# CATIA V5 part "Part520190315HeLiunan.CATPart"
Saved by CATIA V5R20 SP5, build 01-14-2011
Part number: 饮料瓶
Bounding box of the stored display mesh (mm): x -25 to 25, y -25 to 27, z 0 to 100
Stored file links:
  E:\180131213何浏楠\Part520190315HeLiunan.CATPart
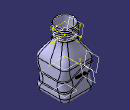
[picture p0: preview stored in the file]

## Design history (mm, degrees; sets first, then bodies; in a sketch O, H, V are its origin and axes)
Set1
  Sketch1 on xy-plane, origin (0, 0, 0), H (1, 0, 0), V (0, 1, 0)
    line L1 (25, 25) -> (25, -25)
    line L2 (25, -25) -> (-25, -25)
    line L3 (-25, -25) -> (-25, 25)
    line L4 (-25, 25) -> (25, 25)
    length L4 = 50
    length L1 = 50
    vertical: L1 V, L3 V
    horizontal: L2 H, L4 H
    equidistance: L1 L3 O, L2 L4 O
  Sketch2 on face of Pad1 from Sketch1.L2, origin (0, -25, 0), H (1, 0, 0), V (0, 0, 1)
    spline S1 through (-40, 20) (-11.6241, 30.786) (12.3742, 19.786) (40, 20)
  Extrude1: Element1 Sketch2, Lim1 69, Lim2 69
  MultiSel1: CommonCtxFeats ({extract ExtractElem face of Fillet1}; {extract ExtractElem face of Pad1 from Sketch1.L1}; {extract ExtractElem face of Pad1 from Sketch1.L2}; {extract ExtractElem face of Fillet1}; {extract ExtractElem face of Fillet1}; {extract ExtractElem face of Pad1 from Sketch1.L4}; {extract ExtractElem face of Fillet1}; {extract ExtractElem face of Pad1 from Sketch1.L3})
  Sketch3 on face of Pad1 from Sketch1.L2, origin (0, -25, 0), H (1, 0, 0), V (0, 0, 1)
    spline S1 through (-30.294, 40.4604) (-11.9151, 45.3274) (15.3659, 35.3071) (46.3801, 31.0127)
  Extrude2: Element1 Sketch3, Lim1 69, Lim2 69
  MultiSel2: CommonCtxFeats ({extract ExtractElem face of Fillet1}; {extract ExtractElem edge [face of Pad1 from Sketch1.L1 | face of Fillet1]}; {extract ExtractElem face of Pad1 from Sketch1.L1}; {extract ExtractElem face of Pad1 from Sketch1.L2}; {extract ExtractElem face of Fillet1}; {extract ExtractElem face of Fillet1}; {extract ExtractElem face of Pad1 from Sketch1.L4}; {extract ExtractElem face of Fillet1}; {extract ExtractElem face of Pad1 from Sketch1.L3})
  Join1: Elements ({intersect ToIntersect1 {extract ExtractElem face of Pad1 from Sketch1.L2}, ToIntersect2 Extrude1}; {intersect ToIntersect1 {extract ExtractElem face of Fillet1}, ToIntersect2 Extrude1}; {intersect ToIntersect1 {extract ExtractElem face of Fillet1}, ToIntersect2 Extrude1}; {intersect ToIntersect1 {extract ExtractElem face of Pad1 from Sketch1.L1}, ToIntersect2 Extrude1}; {intersect ToIntersect1 {extract ExtractElem face of Fillet1}, ToIntersect2 Extrude1}; {intersect ToIntersect1 {extract ExtractElem face of Pad1 from Sketch1.L4}, ToIntersect2 Extrude1}; {intersect ToIntersect1 {extract ExtractElem face of Fillet1}, ToIntersect2 Extrude1}; {intersect ToIntersect1 {extract ExtractElem face of Pad1 from Sketch1.L3}, ToIntersect2 Extrude1})
  Join2: Elements ({intersect ToIntersect1 {extract ExtractElem face of Pad1 from Sketch1.L2}, ToIntersect2 Extrude2}; {intersect ToIntersect1 {extract ExtractElem face of Fillet1}, ToIntersect2 Extrude2}; {intersect ToIntersect1 {extract ExtractElem face of Pad1 from Sketch1.L1}, ToIntersect2 Extrude2}; {intersect ToIntersect1 {extract ExtractElem face of Fillet1}, ToIntersect2 Extrude2}; {intersect ToIntersect1 {extract ExtractElem face of Pad1 from Sketch1.L4}, ToIntersect2 Extrude2}; {intersect ToIntersect1 {extract ExtractElem face of Fillet1}, ToIntersect2 Extrude2}; {intersect ToIntersect1 {extract ExtractElem face of Pad1 from Sketch1.L3}, ToIntersect2 Extrude2}; {intersect ToIntersect1 {extract ExtractElem face of Fillet1}, ToIntersect2 Extrude2})
  Plane1: type Normal, Curve Join2, RefPoint vertex [face of MultiSel2 | face of MultiSel2]
  Circle1: type CtrRad, Start 0, End 180, Center vertex [face of MultiSel2 | face of MultiSel2], Support Plane1, Radius 1, FirstDirection (0, 1, 0)
Body1 (main body)
  Pad1: profile Sketch1, direction (0, 0, 1), length 50
  Fillet1: on edge [face of Pad1 from Sketch1.L3 | face of Pad1 from Sketch1.L4]; edge [face of Pad1 from Sketch1.L1 | face of Pad1 from Sketch1.L2]; edge [face of Pad1 from Sketch1.L4 | face of Pad1 from Sketch1.L1]; edge [face of Pad1 from Sketch1.L2 | face of Pad1 from Sketch1.L3]
  Fillet2: on edge [start face of Pad1 | face of Fillet1]
  Plane2: type Offset, RefPlane xy-plane, Offset 40
  Plane3: type Offset, RefPlane Plane2, Offset 40
  Sketch4 on Plane3, origin (0, 0, 80), H (1, 0, 0), V (0, 1, 0)
    circle A1 centre (0, 0) radius 15
    radius A1 = 15
  Pad2: profile Sketch4, direction (0, 0, 1), length 20
  Sketch5 on end face of Pad1, origin (0, 0, 50), H (1, 0, 0), V (0, 1, 0)
    point P1 (25, 0)
    distance V P1 = 25
    coincidence: P1 H
  Sketch6 on start face of Pad2, origin (0, 0, 80), H (1, 0, 0), V (0, -1, 0)
    point P1 (15, 0)
    distance V P1 = 15
    coincidence: P1 H
  Loft1: solid, Sections ({boundary Boundary {extract ExtractElem end face of Pad1}}; {boundary Boundary {extract ExtractElem start face of Pad2}}), StartFace end face of Pad1, EndFace start face of Pad2
  Slot1: profile Circle1, centre curve Join2
  Plane4: type Normal, Curve Join1, RefPoint vertex [face of MultiSel1 | face of MultiSel1]
  Circle2: type CtrRad, Start 0, End 180, Center vertex [face of MultiSel1 | face of MultiSel1], Support Plane4, Radius 1, FirstDirection (0, 1, 0)
  Slot2: profile Circle2, centre curve Join1
  Shell1: ExtOffset 0, Face end face of Pad2, IntOffset 1
  Plane5: type Offset, RefPlane Plane3, Offset 2
  Sketch7 on Plane5, origin (0, 0, 82), H (1, 0, 0), V (0, 1, 0)
    point P1 (15, 0)
    distance P1 V = 15
    coincidence: P1 H
  Helix1: Direction Z axis, RefPoint Sketch7, Pitch 3, Height 16, TaperAngle 0
  Line1: type PtDir, RefPoint vertex of Helix1, Direction (0, 1, 0), Start 0, End 10
  Line2: type PtDir, RefPoint Sketch7, Direction {line type PtDir, RefPoint Sketch7, Direction (1, 0, 0), Start 0, End 10}, Start 0, End 10
  Point1: type OnCurve, Support Helix1, Length 5
  Point2: type OnCurve, Support Helix1, RefPoint vertex of Helix1, Length 498.79
  Connect1: Curve1 Line2, Point1 vertex of Line2, Tension1 1, Curve2 Helix1, Point2 Point2, Tension2 1
  Connect2: Curve1 Line1, Point1 vertex of Line1, Tension1 1, Curve2 Connect1, Point2 Point1, Tension2 1
  Plane6: type Normal, Curve Connect2, RefPoint Point1
  Sketch8 on Plane6, origin (-3.055, -0.5889, 0.099), H (-0.1893, 0.9819, 0), V (0.0312, 0.006, 0.9995)
    circle A1 centre (15.1102, 97.7456) radius 1
    radius A1 = 1
  Rib1: profile Sketch8, centre curve Connect2
  Body2
    Sketch9 on Plane3, origin (0, 0, 80), H (1, 0, 0), V (0, 1, 0)
      circle A1 centre (0, 0) radius 14
      radius A1 = 14
    Pad3: profile Sketch9, direction (0, 0, 1), length 30
  Remove1: tool Body2
Body3
  Sketch10 on end face of Pad2, origin (0, 0, 100), H (1, 0, 0), V (0, 1, 0)
    circle A1 centre (0, 0) radius 14
    point P1 (14, 0)
    radius A1 = 14
    coincidence: A1 P1, P1 H
Body4
  Sketch11 on face of Pad1 from Sketch1.L4, origin (0, 25, 0), H (-1, 0, 0), V (0, 0, 1)
    polyline C1
    polyline C2
    polyline C3
    polyline C4
    polyline C5
    polyline C6
    polyline C7
    polyline C8
    polyline C9
    polyline C10
    polyline C11
    polyline C12
    polyline C13
  Pad4: profile Sketch11, direction (0, 1, 0), length 2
